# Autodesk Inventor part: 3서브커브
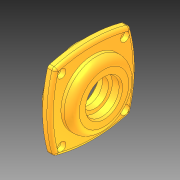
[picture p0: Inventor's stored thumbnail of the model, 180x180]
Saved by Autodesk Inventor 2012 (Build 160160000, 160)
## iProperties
Created: 2012-07
Part Number: 3서브커브
Material: Default
Document SubType Name: Modeling
Designer: JANG KYOUNG-IL
Density: 1 g/cm^3
Author: JANG KYOUNG-IL
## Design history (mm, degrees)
node "작업축1"
node "작업 평면2"
node "작업점1"
sketch "스케치12"
  geometry: L1 (-46.5, 57.5)-(-72.5, 57.5); L2 (-46.5, 90)-(-55.5, 90); L3 (-55.5, 90)-(-55.5, 87.5); L4 (-55.5, 87.5)-(-72.5, 87.5); L5 (-72.5, 87.5)-(-72.5, 73.5); L6 (-72.5, 73.5)-(-64.2, 73.5); L7 (-64.2, 73.5)-(-64.2, 70); L8 (-64.2, 70)-(-58.5, 70); L9 (-58.5, 70)-(-58.5, 77.5); L10 (-58.5, 77.5)-(-46.5, 77.5); L11 (-46.5, 77.5)-(-46.5, 90); 1 further point
  constraints: 22 end point, 8 parallel, 4 point on line, 2 vertical, 1 horizontal
  dimensions: "d87" = 8.3 horizontal distance of L7.end L5.end; "d88" = 12 horizontal distance of L8.end L10.end; "d89" = 25 diameter of L8 L1; "d90" = 32 diameter of L6 L1; "d91" = 40 diameter of L10 L1; "d92" = 65 diameter of L2 L1; "d93" = 60 diameter of L4 L1; "d95" = 9 distance of L2.start L2.end; "d96" = 26 horizontal distance of L4.end L2.start
revolve "회전1" sketch "스케치12" stored, may be unused: angle "d97" = 90 deg
sketch "스케치13"
  geometry: L1 (-35.002, 92.502)-(35.002, 92.502); L2 (35.002, 92.502)-(35.002, 22.498); L3 (35.002, 22.498)-(-35.002, 22.498); L4 (-35.002, 22.498)-(-35.002, 92.502); C1 r 20 at (0, 57.5) reference; A1 r 125.055 centre (0, -27.555) between (35.002, 92.502) and (-35.002, 92.502); A2 r 125.055 centre (0, 142.555) between (-35.002, 22.498) and (35.002, 22.498); A3 r 125.055 centre (85.055, 57.5) between (-35.002, 92.502) and (-35.002, 22.498); A4 r 125.055 centre (-85.055, 57.5) between (35.002, 22.498) and (35.002, 92.502); 4 further points
  constraints: 8 end point, 8 point on circle, 4 centre point, 2 equal radius, 2 midpoint, 2 parallel, 2 perpendicular, 1 horizontal, 1 horizontal alignment, 1 vertical alignment
  dimensions: "d98" = 99 distance of L1.end L3.end; "d99" = 80 dimension on A2 A1; "d100" = 80 dimension on A4 A3
extrude "돌출10" join sketch "스케치13" distance "d101" = 7; taper "d102" = 0 deg
fillet "모깎기7" dims "d103" = 7
chamfer "모따기2" distance "d104" = 2; stored, may be unused: second distance "d105" = 2, angle "d106" = 30 deg
fillet "모깎기8" dims "d107" = 0.3
chamfer "모따기3" distance "d108" = 2; stored, may be unused: second distance "d109" = 2, angle "d110" = 30 deg
sketch "스케치14"
  geometry: L1 (-57.5, 0)-(-99, 0); A1 r 41.5 centre (-57.5, 0) between (-86.845, 29.345) and (-99, 0); 2 further points
  constraints: 2 end point, 2 point on circle, 1 centre point, 1 coincident, 1 horizontal
  dimensions: "d111" = 45 deg dimension on point (-57.5, 0) L1.end A1.start; "d120" = 83 diameter of A1
hole "구멍3" sketch "스케치14" at (-57.5, 0), (-86.845, 29.345) diameter "d112" = 4.5; stored, may be unused: countersink angle "d116" = 90 deg, drill point angle "d118" = 118 deg; dims "d113" = 6, "d114" = 8, "d115" = 4.4, "d117" = 8
node "작업 평면3"
chamfer "모따기4" distance "d121" = 1; stored, may be unused: second distance "d122" = 2, angle "d123" = 45 deg
fillet "모깎기9" dims "d124" = 3
node "솔리드1"
mirror "대칭3"
mirror "대칭4"
node "솔리드3"
other parameters: "d83" = 55.5, "d119" = 90 deg
